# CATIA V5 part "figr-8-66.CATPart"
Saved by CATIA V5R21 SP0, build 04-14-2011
Part number: Part1
Bounding box of the stored display mesh (mm): x -53.439 to 53.439, y -63.41 to 63.41, z -17.5 to 17.5
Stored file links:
  D:\CATIA V5R21 E-RESOURCES\CATIA-V5R21\catia-v5r21-prt\c08-catia-v5r20-prt\c08-catia-v5r21-figr-8-66.CATPart
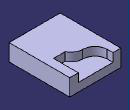
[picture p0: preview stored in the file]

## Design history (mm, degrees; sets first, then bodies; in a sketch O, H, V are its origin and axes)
Body1 (main body)
  Sketch1 on xy-plane, origin (0, 0, 0), H (1, 0, 0), V (0, 1, 0)
    line L1 (-53.4395, 63.4095) -> (53.4395, 63.4095)
    line L2 (53.4395, 63.4095) -> (53.4395, -63.4095)
    line L3 (53.4395, -63.4095) -> (-53.4395, -63.4095)
    line L4 (-53.4395, -63.4095) -> (-53.4395, 63.4095)
    axis line L5 (53.4395, -63.4095) -> (-53.4395, 63.4095)
    horizontal: L1 H, L3 H
    vertical: L2 V, L4 V
    midpoint: O L5
  Pad1: profile Sketch1, direction (0, 0, 1), length 17.5, mirrored extent
  Body2
    Sketch2 on xy-plane, origin (0, 0, 0), H (1, 0, 0), V (0, 1, 0)
      line L1 (-36.9238, 103.6333) -> (-36.9238, 51.4035)
      arc A1 centre (-11.4307, 51.4035) radius 25.4931 from (-36.9238, 51.4035) to (-11.4307, 25.9104) ccw
      arc A2 centre (-11.4307, 0.4172) radius 25.4931 from (-11.4307, 25.9104) to (11.4981, 11.5602) cw
      line L2 (11.4981, 11.5602) -> (35.6176, 11.5602)
      line L3 (35.6176, 11.5602) -> (35.6176, 103.6333)
      line L4 (35.6176, 103.6333) -> (-36.9238, 103.6333)
      vertical: L1 V, L3 V
      tangency: A1 L1, A2 L1, A2 A1
      horizontal: L2 H, L4 H
    Pad2: profile Sketch2, direction (0, 0, 1), length 34.5
  Remove1: tool Body2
